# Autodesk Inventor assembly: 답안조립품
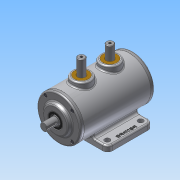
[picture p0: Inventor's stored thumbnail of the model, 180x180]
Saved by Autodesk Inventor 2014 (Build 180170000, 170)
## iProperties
Created: 2014-12
Part Number: 답안조립품
Document SubType Name: Assembly
Designer: Owner
Author: Owner
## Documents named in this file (10)
- C:\Users\Owner\Desktop\441223V1014\답안조립품.iam
- C:\Users\Owner\Desktop\441223V1014\1-본체.ipt
- C:\Users\Owner\Desktop\441223V1014\4-축.ipt
- C:\Users\Owner\Desktop\441223V1014\M4-소켓머리.ipt
- C:\Users\Owner\Desktop\441223V1014\뒷커버.ipt
- C:\Users\Owner\Desktop\441223V1014\베어링 6203.ipt
- C:\Users\Owner\Desktop\441223V1014\부시.ipt
- C:\Users\Owner\Desktop\441223V1014\슬라이더.ipt
- C:\Users\Owner\Desktop\441223V1014\앞커버.ipt
- C:\Users\Owner\Desktop\441223V1014\오일실.ipt
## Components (13 placed, 5 different names)
1. 1-본체:1
2. 4-축:1
3. 7-베어링 6203:1
4. 8-오일실:1
5. 7-베어링 6203:2
6. 9-M4-소켓머리:2
7. 9-M4-소켓머리:3
8. 9-M4-소켓머리:4
9. 9-M4-소켓머리:5
10. 9-M4-소켓머리:1
11. 9-M4-소켓머리:6
12. 9-M4-소켓머리:7
13. 9-M4-소켓머리:8
